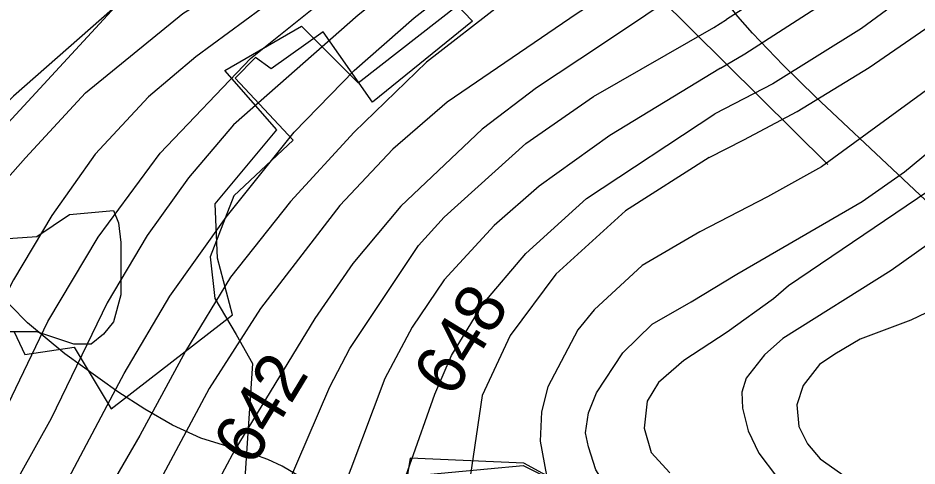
# Model space of a CAD drawing. Extents: x -709584 to -702006, y -1161789 to -1157496.
# Drawn here: x -706813.4 to -706631.4, y -1159940.6 to -1159849.8 of the extents above; entities that cross this region are included whole.
import ezdxf

# ---------------------------------------------------------------- set-up
doc = ezdxf.new("R2010")
doc.units = 0
for name, color, linetype in [('102_obvod PÚ', 7, 'Continuous'), ('120_vrstevnice hlavní', 7, 'Continuous'), ('121_vrstevnice hlavní_popis', 7, 'Continuous'), ('122_vrstevnice základní', 7, 'Continuous'), ('408_BPEJ_linie', 7, 'Continuous'), ('411_akumulovaný odtok', 7, 'Continuous'), ('419_LPIS PB', 7, 'Continuous')]:
    doc.layers.add(name, color=color, linetype=linetype)

msp = doc.modelspace()

# ---------------------------------------------------------------- linework, layer by layer
at = {"layer": '102_obvod PÚ'}
for points in [[(-706610.14, -1159730.65), (-706648.39, -1159762.04), (-706648.03, -1159765), (-706661.44, -1159800.87), (-706686.33, -1159816.5), (-706683.85, -1159821.64), (-706716.26, -1159841.8), (-706724.22, -1159836.52), (-706730.29, -1159841.19), (-706721.4, -1159850.47), (-706741.6, -1159866.92), (-706751.59, -1159852.64), (-706762.11, -1159860.17), (-706765.29, -1159857.85), (-706769.46, -1159862.06), (-706757.69, -1159874.59), (-706769.71, -1159885.84), (-706774.49, -1159898.23)], [(-706774.49, -1159898.23), (-706773.55, -1159906.69), (-706769.21, -1159913.96), (-706765.89, -1159919.81), (-706767.6, -1159945.07)], [(-706732.76, -1159942.52), (-706711.1, -1159940.48), (-706676.68, -1159957.85)]]:
    msp.add_lwpolyline(points, dxfattribs=at)
at = {"layer": '120_vrstevnice hlavní'}
for points in [[(-706673.46, -1159878.09), (-706666.48, -1159874.54), (-706655.69, -1159868.79), (-706641.09, -1159859.89), (-706629.65, -1159851.95), (-706617.54, -1159841.4), (-706606.14, -1159829.86), (-706601.3, -1159824.16), (-706573.8, -1159787.26), (-706564.39, -1159775.86), (-706553.7, -1159765.6), (-706541.45, -1159755.62), (-706532.9, -1159749.78), (-706518.94, -1159741.52), (-706508.82, -1159737.53), (-706492.72, -1159733.39), (-706481.89, -1159731.68), (-706471.06, -1159731.26), (-706465.64, -1159731.68), (-706455.38, -1159734.53)], [(-706720.57, -1159816.24), (-706754.24, -1159840.65), (-706777.42, -1159857.69), (-706786.98, -1159865.84), (-706797.79, -1159877.42), (-706806.52, -1159889.82), (-706814.32, -1159902.85), (-706826.3, -1159926.72), (-706838.7, -1159948.78), (-706850.08, -1159968), (-706864.28, -1159986.25), (-706881.73, -1160002.84), (-706892.86, -1160013.54), (-706901.83, -1160023.23), (-706910.65, -1160034.37), (-706914.99, -1160040.88), (-706920.63, -1160053.9), (-706926.28, -1160071.26), (-706944.21, -1160137.5), (-706945.95, -1160149.65)], [(-706667.19, -1159827.83), (-706700.2, -1159848.94), (-706726.52, -1159866.87), (-706737.52, -1159876.42), (-706748.22, -1159887.84), (-706764.27, -1159908.68), (-706774.69, -1159924.87), (-706799.13, -1159970.58)], [(-706673.46, -1159878.09), (-706690.41, -1159888.93), (-706704.54, -1159901.73), (-706713.79, -1159914.17), (-706719.43, -1159926.32), (-706721.89, -1159942.81)], [(-706626.44, -1159908.11), (-706632.65, -1159911.08), (-706642.91, -1159914.93), (-706648.04, -1159917.92), (-706651.12, -1159920.02), (-706654.48, -1159924.28), (-706655.73, -1159928.18), (-706655.3, -1159932.6), (-706653.58, -1159936.07), (-706651.03, -1159939.16)], [(-706651.03, -1159939.16), (-706635.92, -1159949.84), (-706629.76, -1159955.45), (-706614.55, -1159973.07), (-706607.42, -1159983.9), (-706591.61, -1160010.97), (-706587.9, -1160016.39), (-706583.77, -1160021.09), (-706571.8, -1160031.78), (-706559.4, -1160039.04), (-706549.14, -1160043.89), (-706538.88, -1160047.59), (-706528.62, -1160049.73), (-706522.56, -1160050.43), (-706513.23, -1160050.3), (-706507.54, -1160049.59), (-706501.61, -1160047.92), (-706496.14, -1160046.17), (-706490.1, -1160043.78), (-706485.88, -1160041.47), (-706476.61, -1160035.34), (-706462.94, -1160024.37), (-706458.38, -1160019.95)]]:
    msp.add_lwpolyline(points, dxfattribs=at)
msp.add_open_spline([(-706673.46, -1159878.09), (-706673.46, -1159878.09)], degree=1, dxfattribs=at)
at = {"layer": '122_vrstevnice základní'}
for points in [[(-706479.99, -1159688.87), (-706496.16, -1159690.14), (-706513.69, -1159694.76), (-706529.21, -1159703.78), (-706537.46, -1159709.46), (-706552.85, -1159723.7), (-706566.67, -1159738.81), (-706583.77, -1159760.04), (-706607, -1159792.81), (-706627.23, -1159816.18), (-706636.21, -1159825.73), (-706646.31, -1159834.43), (-706656.76, -1159841.61), (-706669.98, -1159850.17)], [(-706650.66, -1159692.43), (-706660.45, -1159706.17), (-706665.61, -1159714.65), (-706676.19, -1159731.72), (-706691.34, -1159755.31), (-706705.07, -1159773.41), (-706716.39, -1159786.43), (-706730.17, -1159799.55), (-706770.72, -1159830.91), (-706789.82, -1159844.1), (-706814.32, -1159865.65), (-706827.19, -1159878.59), (-706833.7, -1159887.12), (-706843.68, -1159904.48), (-706859.29, -1159932.03), (-706872.34, -1159951.47)], [(-706671.2, -1159859.99), (-706666.27, -1159857.08), (-706647.89, -1159845.25), (-706630.08, -1159830.29), (-706620.53, -1159820.17), (-706612.13, -1159810.2), (-706583.34, -1159773.29), (-706567.24, -1159754.91), (-706552.56, -1159740.66), (-706531.05, -1159723.56), (-706515.09, -1159713.59), (-706496.99, -1159705.32), (-706487.42, -1159702.71), (-706468.49, -1159703.9), (-706450.25, -1159708.74)], [(-706461.18, -1159719.14), (-706468.49, -1159717.72), (-706478.47, -1159716.86), (-706488.44, -1159717.43), (-706496.42, -1159719), (-706510.39, -1159724.13), (-706518.37, -1159727.69), (-706534.33, -1159737.1), (-706548, -1159747.36), (-706562.96, -1159761.32), (-706572.23, -1159772.15), (-706588.33, -1159793.38), (-706612.7, -1159823.88), (-706627.23, -1159839.98), (-706631.22, -1159843.54), (-706642.62, -1159851.95), (-706660.58, -1159863.21), (-706672.35, -1159869.23)], [(-706677.11, -1159907.35), (-706667.85, -1159901.71), (-706642.48, -1159887), (-706633.93, -1159881.02), (-706617.97, -1159867.77), (-706601.44, -1159851.95), (-706588.76, -1159838.27), (-706570.52, -1159814.62), (-706563.39, -1159805.5), (-706548.57, -1159788.68), (-706541.16, -1159781.84), (-706528.91, -1159771.87), (-706512.67, -1159760.75), (-706504.12, -1159756.05), (-706498.41, -1159753.11), (-706488.58, -1159749.85), (-706484.45, -1159749.5), (-706477.6, -1159749.6), (-706472.77, -1159750.49), (-706467.39, -1159751.86), (-706460.8, -1159754.77)], [(-706457.09, -1159766.74), (-706462.79, -1159763.6), (-706470.49, -1159761.18), (-706475.62, -1159760.61), (-706485.88, -1159761.18), (-706493.57, -1159762.89), (-706501.27, -1159765.74), (-706508.96, -1159770.16), (-706524.07, -1159781.13), (-706540.17, -1159795.52), (-706555.56, -1159810.91), (-706589.75, -1159849.1), (-706605.14, -1159864.49), (-706619.39, -1159877.31), (-706629.23, -1159885.01), (-706657.44, -1159904.1), (-706660.43, -1159906.73), (-706669.81, -1159913.46), (-706678.59, -1159919.21)], [(-706901.94, -1160034.93), (-706878.5, -1160015.52), (-706849.61, -1159986.78), (-706841.37, -1159975.5), (-706821.12, -1159939.85), (-706807.38, -1159911.34), (-706797.19, -1159894.26), (-706784.64, -1159877.2), (-706766.31, -1159858.07), (-706742.37, -1159838.77), (-706703.06, -1159810.72), (-706686.98, -1159797.26), (-706669.15, -1159780.66)], [(-706662, -1159786.17), (-706683.4, -1159804.81), (-706723.19, -1159832.42), (-706744.52, -1159849.25), (-706769.77, -1159871.5), (-706778.88, -1159882.2), (-706787.27, -1159893.92), (-706795.37, -1159907.52), (-706806.65, -1159930.95), (-706831.53, -1159975.5), (-706839.2, -1159986.93), (-706849.9, -1159999.37), (-706851.78, -1160002.55), (-706882.16, -1160027.72)], [(-706836.28, -1160005.21), (-706833.85, -1159994.16), (-706822.42, -1159977.24), (-706813.45, -1159962.48), (-706793.49, -1159924.87), (-706791.9, -1159921.84), (-706782.65, -1159906.17), (-706771.22, -1159890.16), (-706757.48, -1159872.95), (-706745.33, -1159860.51), (-706733.18, -1159849.8), (-706722.04, -1159841.12), (-706703.81, -1159828.83), (-706688.1, -1159817.93), (-706675.8, -1159808.84), (-706663.54, -1159798.55)], [(-706664.92, -1159809.65), (-706676.56, -1159818.59), (-706701.5, -1159837.65), (-706715.38, -1159846.91), (-706730.72, -1159858.77), (-706745.33, -1159872.95), (-706758.2, -1159886.98), (-706770.35, -1159902.31), (-706779.46, -1159917.35), (-706788.72, -1159934.42), (-706814.03, -1159978.1), (-706818.08, -1159984.03), (-706819.82, -1159995.61)], [(-706848.67, -1159942.59), (-706839.9, -1159927.05), (-706831.63, -1159911.52), (-706822.83, -1159894.4), (-706816.99, -1159883.99), (-706811.86, -1159878.15), (-706799.71, -1159864.99), (-706780.04, -1159848.94), (-706776.28, -1159846.62), (-706725.76, -1159810.42)], [(-706586.19, -1159823.17), (-706594.31, -1159832.71), (-706610.42, -1159848.81), (-706626.23, -1159862.07), (-706650.74, -1159880.02), (-706661.65, -1159886.04), (-706675.34, -1159893.19)], [(-706668.36, -1159837.21), (-706695.28, -1159855.3), (-706708.44, -1159863.98), (-706719.43, -1159872.37), (-706735.92, -1159887.99), (-706745.62, -1159899.56), (-706753.28, -1159910.7), (-706769.48, -1159937.31), (-706773.68, -1159945.12)], [(-706759.21, -1159945.41), (-706750.24, -1159924.58), (-706746.19, -1159916.78), (-706732.31, -1159895.95), (-706727.1, -1159890.16), (-706710.61, -1159875.26), (-706696.87, -1159865.72), (-706672.52, -1159851.77), (-706669.98, -1159850.17)], [(-706671.2, -1159859.99), (-706693.59, -1159873.61), (-706707.86, -1159883.94), (-706716.98, -1159891.9), (-706727.1, -1159902.89), (-706733.61, -1159912.44), (-706739.11, -1159922.85), (-706748.36, -1159947.44)], [(-706739.11, -1159954.67), (-706728.98, -1159926.03), (-706725.65, -1159918.22), (-706719.29, -1159907.81), (-706710.61, -1159897.54), (-706698.32, -1159886.4), (-706672.36, -1159869.23)], [(-706675.34, -1159893.19), (-706687.01, -1159899.98), (-706696.73, -1159908.96), (-706700.05, -1159913.01), (-706706.13, -1159924.58), (-706707.43, -1159929.65), (-706707.72, -1159935.58), (-706706.42, -1159942.52), (-706704.25, -1159947.15), (-706699.76, -1159954.09), (-706696.44, -1159961.04), (-706694.12, -1159967.98), (-706692.39, -1159977.24), (-706692.39, -1159981.86), (-706693.54, -1159988.81), (-706697.01, -1159998.06), (-706700.34, -1160005.01), (-706701.5, -1160009.64), (-706701.93, -1160014.27), (-706701.21, -1160021.21), (-706700.05, -1160025.84), (-706693.4, -1160037.95)], [(-706628.94, -1159895.55), (-706636.64, -1159900.97), (-706658.58, -1159914.79), (-706662.28, -1159918.07), (-706665.99, -1159922.77), (-706666.89, -1159925.66), (-706666.7, -1159928.9), (-706665.56, -1159933.46), (-706663.42, -1159938.02), (-706656.3, -1159947.42)], [(-706683.72, -1159960.36), (-706694.12, -1159944.98), (-706696.44, -1159941.36), (-706697.88, -1159936.74), (-706698.52, -1159933.9), (-706697.88, -1159929.79), (-706696.29, -1159925.74), (-706690.94, -1159917.64), (-706685.01, -1159911.86), (-706677.11, -1159907.35)], [(-706678.59, -1159919.21), (-706683.76, -1159923.67), (-706686.02, -1159927.48), (-706686.65, -1159932.91), (-706685.21, -1159937.83), (-706681.43, -1159942.01)]]:
    msp.add_lwpolyline(points, dxfattribs=at)
for points in [[(-706669.98, -1159850.17), (-706669.98, -1159850.17)], [(-706671.2, -1159859.99), (-706671.2, -1159859.99)], [(-706672.36, -1159869.23), (-706672.35, -1159869.23)], [(-706675.34, -1159893.19), (-706675.34, -1159893.19)], [(-706677.11, -1159907.35), (-706677.11, -1159907.35)], [(-706678.59, -1159919.21), (-706678.59, -1159919.21)]]:
    msp.add_open_spline(points, degree=1, dxfattribs=at)
at = {"layer": '408_BPEJ_linie'}
for points in [[(-706814.18, -1159913.42), (-706812, -1159918), (-706802, -1159916.5), (-706794.5, -1159929), (-706770, -1159910), (-706773, -1159898.5), (-706773.5, -1159887.5), (-706761, -1159872.5), (-706771.5, -1159860.5), (-706756, -1159851.5), (-706744.5, -1159863), (-706724, -1159847), (-706730, -1159838.5), (-706727, -1159832.5), (-706715.5, -1159837.5), (-706689, -1159821), (-706690, -1159816.5), (-706666, -1159799), (-706654, -1159765.5), (-706584.5, -1159716)], [(-706678, -1159958), (-706711, -1159940), (-706734, -1159939), (-706735.82, -1159950.21)]]:
    msp.add_lwpolyline(points, dxfattribs=at)
at = {"layer": '411_akumulovaný odtok'}
for points in [[(-706649.49, -1159879.5), (-706683.84, -1159845.33), (-706688.36, -1159840.5), (-706690.34, -1159837.93), (-706691.89, -1159835.11), (-706693.44, -1159830.4), (-706694.64, -1159824.89), (-706696.99, -1159812)], [(-706578.97, -1159941.33), (-706581.9, -1159939.17), (-706584.65, -1159936.67), (-706587.19, -1159933.89), (-706589.5, -1159930.87), (-706594.43, -1159923.25), (-706596.95, -1159919.81), (-706599.71, -1159916.44), (-706605.7, -1159909.87), (-706618.63, -1159897.12), (-706651.98, -1159865.78), (-706658.49, -1159859.42), (-706664.73, -1159852.89), (-706667.67, -1159849.51), (-706670.45, -1159845.95), (-706678.48, -1159834.2), (-706684.58, -1159825.92), (-706690.55, -1159818.77), (-706695.09, -1159813.81), (-706696.99, -1159812)], [(-706706.99, -1159982), (-706740.95, -1159953.94), (-706748.9, -1159947.75), (-706754.31, -1159943.94), (-706759.9, -1159940.64), (-706762.81, -1159939.3), (-706765.48, -1159938.33), (-706776.36, -1159934.98), (-706782.13, -1159932.34), (-706787.72, -1159929.1), (-706793.2, -1159925.54), (-706803.88, -1159917.85), (-706811.5, -1159911.56), (-706818.44, -1159904.6), (-706826.04, -1159895.97), (-706841.99, -1159877)]]:
    msp.add_lwpolyline(points, dxfattribs=at)
at = {"layer": '419_LPIS PB'}
for points in [[(-706601.4, -1159708.5), (-706632.6, -1159734.2), (-706683.9, -1159776), (-706717.46, -1159790.08), (-706733.82, -1159797.19), (-706751.81, -1159805.66), (-706776.5, -1159822.24), (-706785.64, -1159838.73), (-706829.24, -1159885.98)], [(-706816.37, -1159894.56), (-706809.6, -1159894.1), (-706802.96, -1159889.62), (-706794.06, -1159888.82), (-706793.06, -1159891.33), (-706792.56, -1159895.34), (-706792.56, -1159905.89), (-706794.06, -1159911.41), (-706796.06, -1159913.92), (-706798.56, -1159915.93), (-706802.07, -1159915.93), (-706809.57, -1159913.42), (-706817.08, -1159913.42)]]:
    msp.add_lwpolyline(points, dxfattribs=at)

# ---------------------------------------------------------------- texts
at = {"layer": '121_vrstevnice hlavní_popis'}
for s, rotation, p in [('648', 58.4627, (-706725.42, -1159927.06)), ('642', 58.7601, (-706765.92, -1159941))]:
    msp.add_text(s, height=10, rotation=rotation, dxfattribs=at).set_placement(p)

doc.saveas('drawing.dxf')
